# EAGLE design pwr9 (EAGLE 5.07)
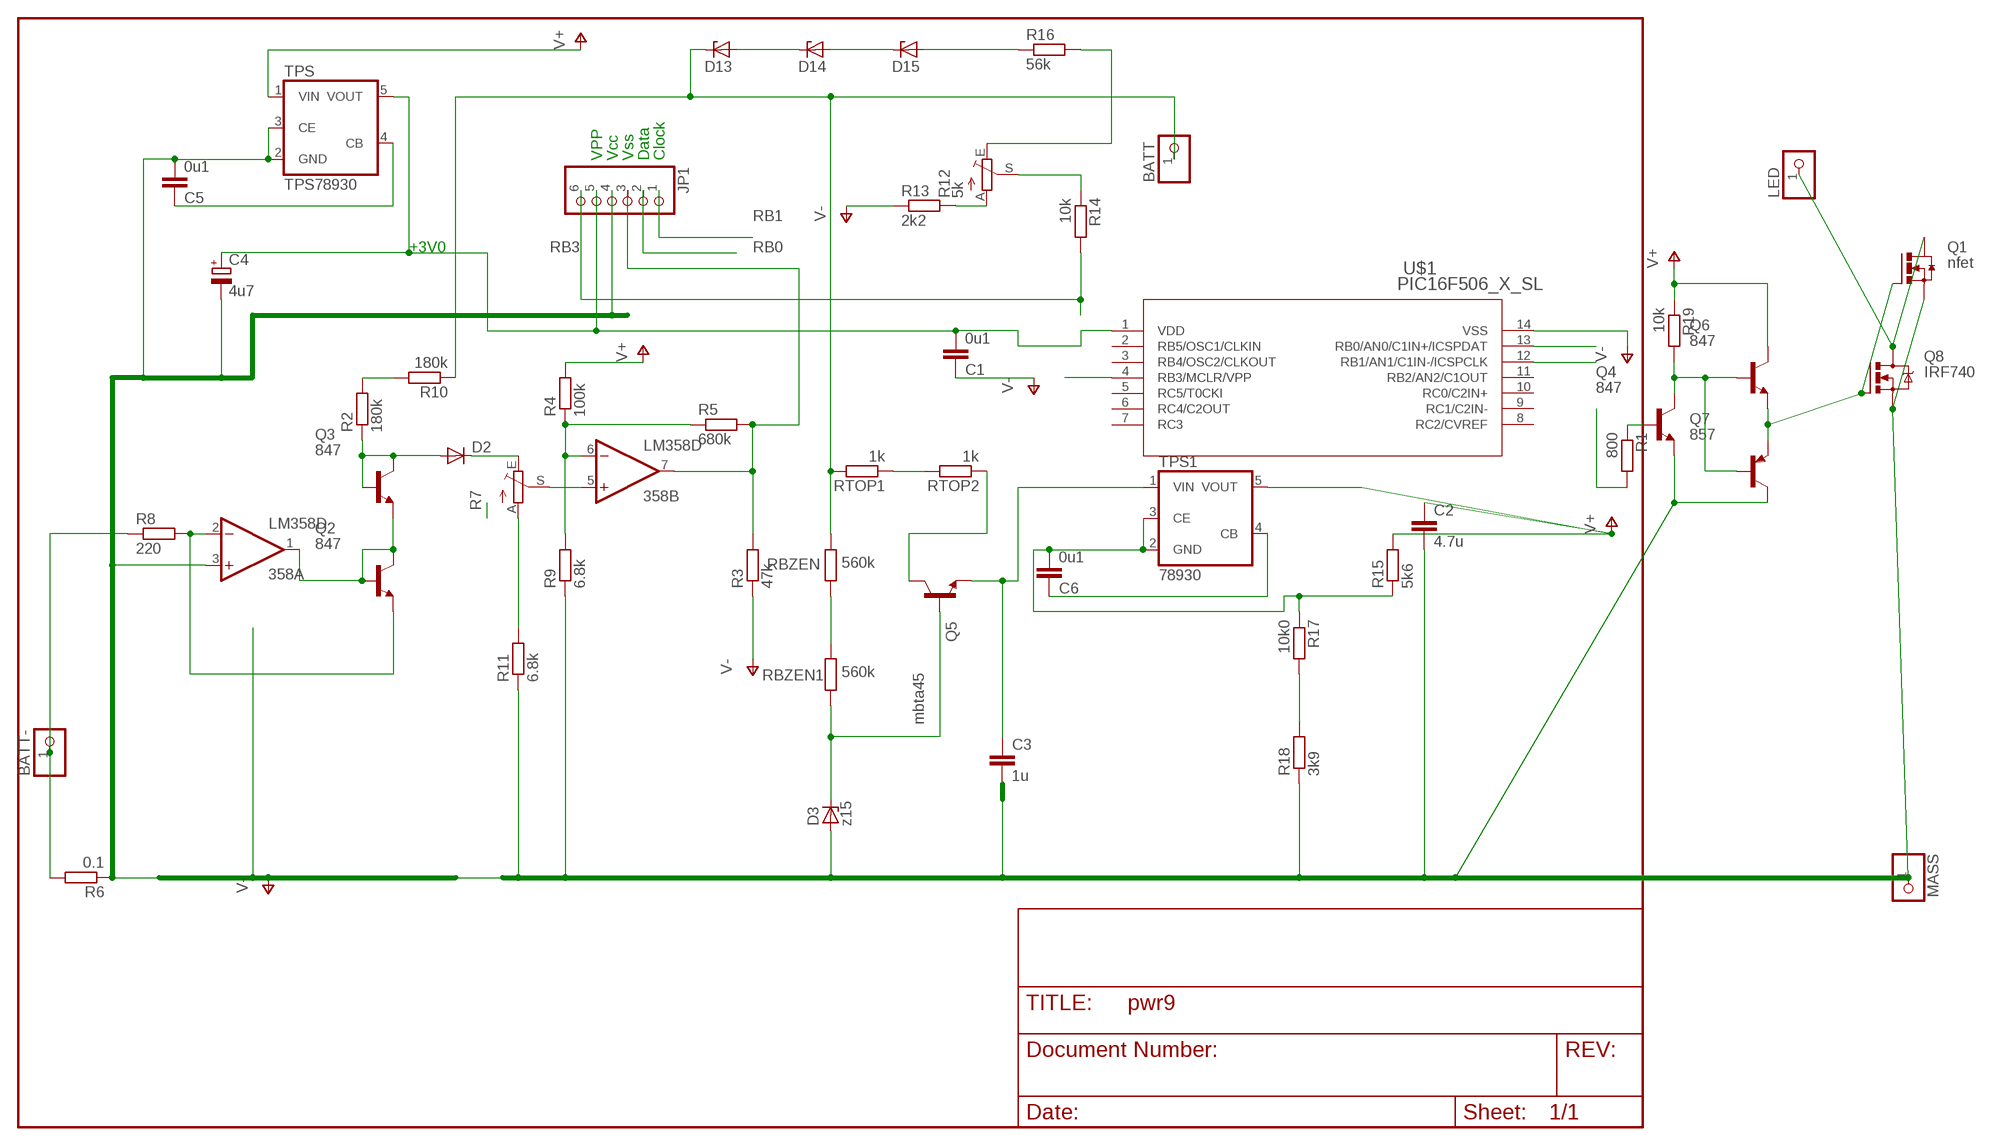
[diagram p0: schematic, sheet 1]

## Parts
358  LM358D  [SO08]
BATT  PINHD-1X1  [1X01]
BATT-  PINHD-1X1  [1X01]
C1  0u1  C-EUC1206  [C1206]
C2  4.7u  C-EUC1206  [C1206]
C3  1u  C-EUC1206  [C1206]
C4  4u7  CPOL-EUSMCA  [SMC_A]
C5  0u1  C-EUC0805  [C0805]
C6  0u1  C-EUC0805  [C0805]
D2  DIODE-SOD80C  [SOD80C]
D3  z15  ZENER-DIODESOD80C  [SOD80C]
D13  ZENER-DIODESOD80C  [SOD80C]
D14  ZENER-DIODESOD80C  [SOD80C]
D15  ZENER-DIODESOD80C  [SOD80C]
JP1  PINHD-1X6  [1X06BOX]
LED  PINHD-1X1  [1X01]
MASS  PINHD-1X1  [1X01]
Q1  nfet  N-HEXFET_DPAK-  [TO252]
Q2  847  BC847ALT1SMD  [SOT23]
Q3  847  BC847ALT1SMD  [SOT23]
Q4  847  BC847ALT1SMD  [SOT23]
Q5  mbta45  BC847ALT1SMD  [SOT23]
Q6  847  BC847ALT1SMD  [SOT23]
Q7  857  BC857ALT1SMD  [SOT23-BEC]
Q8  IRF740  [TO220BV]
R1  800  R-EU_R0805  [R0805]
R2  180k  R-EU_R1206  [R1206]
R3  47k  R-EU_R0805  [R0805]
R4  100k  R-EU_R0805  [R0805]
R5  680k  R-EU_R1206  [R1206]
R6  0.1  R-EU_R2512  [R2512]
R7  TRIM_EU-S64W  [S64W]
R8  220  R-EU_R0805  [R0805]
R9  6.8k  R-EU_R0805  [R0805]
R10  180k  R-EU_R1206  [R1206]
R11  6.8k  R-EU_R0805  [R0805]
R12  5k  TRIM_EU-S64W  [S64W]
R13  2k2  R-EU_R0805  [R0805]
R14  10k  R-EU_R0805  [R0805]
R15  5k6  R-EU_R0805  [R0805]
R16  56k  R-EU_R0805  [R0805]
R17  10k0  R-EU_R0805  [R0805]
R18  3k9  R-EU_R0805  [R0805]
R19  10k  R-EU_R0805  [R0805]
RBZEN  560k  R-EU_R1206  [R1206]
RBZEN1  560k  R-EU_R1206  [R1206]
RTOP1  1k  R-EU_R1206  [R1206]
RTOP2  1k  R-EU_R1206  [R1206]
TPS  TPS78930  TPS78930SOT23-5  [SOT25]
TPS1  78930  TPS78930SOT23-5  [SOT25]
U$1  PIC16F506_X_SL  [SOIC14_N_MC]

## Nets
CB: D3.C Q5.1(B) RBZEN1.2
GND1: C6.1 TPS1.4(CB)
HOT: LED.1 Q1.3(D) Q8.D
N$1: Q4.1(B) R1.1
N$2: R7.A R11.2
N$3: BATT-.1 R6.2 R8.1
N$4: 358.7(B:OUT) JP1.3 R3.2 R5.2
N$5: R1.2
N$6: R2.2 R10.2
N$7: 358.1(A:OUT) Q2.1(B) Q2.3(C) Q3.2(E)
N$9: C1.2 C4.+ JP1.5 TPS.5(VOUT) U$1.1(VDD)
N$10: 358.2(A:-IN) Q2.2(E) R8.2
N$11: C5.1 TPS.4(CB)
N$12: D2.A Q3.1(B) Q3.3(C) R2.1
N$13: D2.C R7.E
N$15: 358.5(B:+IN) R7.S
N$16: Q5.3(C) RTOP2.1
N$17: 358.6(B:-IN) R4.1 R5.1 R9.2
N$18: D15.A R16.1
N$19: RBZEN1.1 RBZEN.2
N$21: Q4.3(C) Q6.1(B) Q7.B R19.2
N$23: D14.A D15.C
N$24: D13.A D14.C
N$25: R12.E R16.2
N$26: R12.A R13.2
N$27: R12.S R14.1
N$28: R17.2 R18.2
N$29: RTOP1.1 RTOP2.2
N$31: Q1.1(G) Q6.2(E) Q7.E Q8.G
RB0: JP1.2 U$1.13(RB0/AN0/C1IN+/ICSPDAT)
RB1: JP1.1 U$1.12(RB1/AN1/C1IN-/ICSPCLK)
RB3: JP1.6 R14.2 U$1.4(RB3/MCLR/VPP)
V15: C3.1 Q5.2(E) TPS1.1(VIN)
V+: C2.1 Q6.3(C) R4.2 R15.2 R19.1 TPS1.5(VOUT) TPS.1(VIN)
V-: 358.3(A:+IN) C1.1 C2.2 C3.2 C4.- C5.2 C6.2 D3.A JP1.4 MASS.1 Q1.2(S) Q4.2(E) Q7.C Q8.S R3.1 R6.1 R9.1 R11.1 R13.1 R15.1 R17.1 R18.1 TPS1.2(GND) TPS1.3(CE) TPS.2(GND) TPS.3(CE) U$1.14(VSS)
VPLUS: BATT.1 D13.C R10.1 RBZEN.1 RTOP1.2
Unconnected: U$1.2(RB5/OSC1/CLKIN) U$1.3(RB4/OSC2/CLKOUT) U$1.5(RC5/T0CKI) U$1.6(RC4/C2OUT) U$1.7(RC3) U$1.8(RC2/CVREF) U$1.9(RC1/C2IN-) U$1.10(RC0/C2IN+) U$1.11(RB2/AN2/C1OUT)

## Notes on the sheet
- VPP | Vcc | Vss | Data | Clock
- +3V0

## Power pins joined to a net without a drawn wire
V+: 358.8(P:V+)
V-: 358.4(P:V-)

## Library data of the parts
358 = linear:LM358: OP AMP also LM158; LM258; LM2904 Source: http://cache.national.com/ds/LM/LM158.pdf
BATT BATT- LED MASS = pinhead:PINHD-1X1: PIN HEADER
C1-C3 C5 C6 = rcl:C-EU: CAPACITOR, European symbol
C4 = rcl(2):CPOL-EU: POLARIZED CAPACITOR, European symbol
D2 = diode:DIODE-: DIODE
D3 D13-D15 = diode:ZENER-DIODE: Z-Diode
JP1 = pinhead:PINHD-1X6: PIN HEADER
Q1 = transistor-power:N-HEXFET_?-*: HEXFET® Power MOSFET
Q2-Q6 = transistor-npn:BC847*: NPN Transistor
Q7 = transistor-pnp:BC857*: PNP Transistror
Q8 = transistor-power:IRF740: N-CHANNEL MOS FET
R1-R6 R8-R11 R13-R19 RBZEN RBZEN1 RTOP1 RTOP2 = rcl:R-EU_: RESISTOR, European symbol
R7 R12 = pot:TRIM_EU-: POTENTIOMETER
TPS TPS1 = v-reg:TPS78930
U$1 = pic16f506mc:PIC16F506_X_SL

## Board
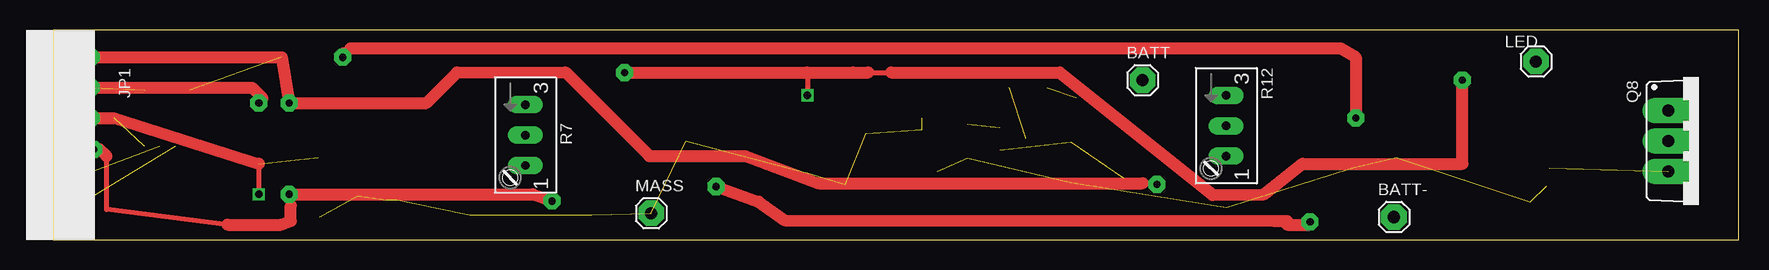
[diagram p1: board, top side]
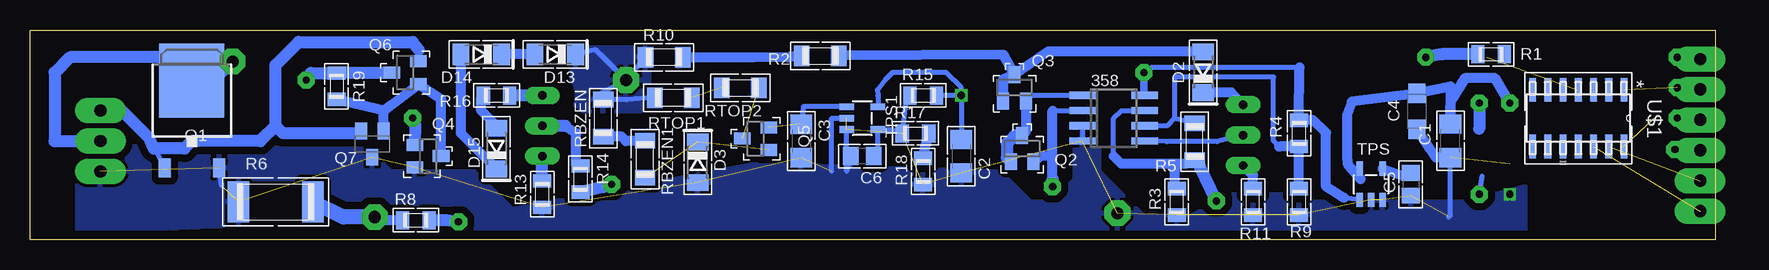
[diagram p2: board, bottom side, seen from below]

Size 140.49 x 17.5 mm. Coordinates in mm from the lower left corner, seen from the top.
Outline: 0,0 140.49,0 140.49,17.5 0,17.5 0,0
Copper layers (1*16): Top 0.035mm / dielectric 1.5mm / Bottom 0.035mm
Design rules "default *": minimum track width 10mil, minimum drill 24mil, track to track 8mil, track to pad 8mil, pad to pad 8mil, via to via 8mil, smd to smd 8mil, copper to edge 30mil, drill to drill 8mil, minimum pad ring 15mil, minimum via ring 8mil, stop-mask expansion 4mil, vias tented up to drill 0mil, thermal gap 10mil

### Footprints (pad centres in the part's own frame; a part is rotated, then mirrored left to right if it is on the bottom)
SO08 = smd 0.6 x 2.2: 1 -1.905,-2.6; 2 -0.635,-2.6; 3 0.635,-2.6; 4 1.905,-2.6; 5 1.905,2.6; 6 0.635,2.6; 7 -0.635,2.6; 8 -1.905,2.6
1X01 = drill 1.016 octagon: 1 0,0
C1206 = smd 1.6 x 1.8: 1 -1.4,0; 2 1.4,0
SMC_A = smd 1.6 x 1.4: + -1.5,0; - 1.5,0
C0805 = smd 1.3 x 1.5: 1 -0.95,0; 2 0.95,0
SOD80C = smd 1.4 x 1.8: A 1.7,0; C -1.7,0
1X06BOX = drill 1.016 long: 1 -6.35,0; 2 -3.81,0; 3 -1.27,0; 4 1.27,0; 5 3.81,0; 6 6.35,0
TO252 = smd 1 x 1.6: 1 -2.28,-3.53; 2 2.28,-3.53 | smd 5.4 x 6.2: 3 0,3.77
SOT23 = smd 1 x 1.4: 1 -0.95,-1.1; 2 0.95,-1.1; 3 0,1.1
SOT23-BEC = smd 1 x 1.4: B -0.95,-1.1; C 0,1.1; E 0.95,-1.1
TO220BV = drill 1.016 long: D 0,-2.54; G -2.54,-2.54; S 2.54,-2.54
R0805 = smd 1.1 x 1.5: 1 -1.1,0; 2 1.1,0
R1206 = smd 1.3 x 1.7: 1 -1.55,0; 2 1.55,0
R2512 = smd 1.8 x 3.4: 1 -3.1,0; 2 3.1,0
S64W = drill 0.7 long: A 2.54,1.27; E -2.54,1.27; S 0,1.27
SOT25 = smd 0.55 x 1.2: 1 -0.95,-1.3; 2 0,-1.3; 3 0.95,-1.3; 4 0.95,1.3; 5 -0.95,1.3
SOIC14_N_MC = smd 1.981 x 0.559: 1 -2.362,3.81; 2 -2.362,2.54; 3 -2.362,1.27; 4 -2.362,0; 5 -2.362,-1.27; 6 -2.362,-2.54; 7 -2.362,-3.81; 8 2.362,-3.81; 9 2.362,-2.54; 10 2.362,-1.27; 11 2.362,0; 12 2.362,1.27; 13 2.362,2.54; 14 2.362,3.81

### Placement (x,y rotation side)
358  50.17,10.16 270 bottom
BATT  90.81,13.34 0 top
BATT-  111.76,1.91 0 top
C1  22.09,8.26 90 bottom
C2  62.86,6.99 270 bottom
C3  76.2,8.26 270 bottom
C4  24.89,10.73 270 bottom
C5  25.4,4.63 270 bottom
C6  71.12,6.99 180 bottom
D2  42.7,14 90 bottom
D3  84.84,6.48 270 bottom
D13  96.71,15.5 180 bottom
D14  102.87,15.5 180 bottom
D15  101.6,7.62 90 bottom
JP1  1.27,8.75 90 top
LED  123.6,14.89 0 top
MASS  49.85,2.22 0 top
Q1  127,9.53 0 bottom
Q2  57.78,7.62 0 bottom
Q3  58.42,12.7 0 bottom
Q4  107.31,6.99 270 bottom
Q5  80.01,8.45 90 bottom
Q6  109.22,13.97 90 bottom
Q7  111.95,8 180 bottom
Q8  137.16,8.26 270 top
R1  18.7,15.5 0 bottom
R2  74.61,15.37 180 bottom
R3  44.89,3.17 90 bottom
R4  34.7,8.89 90 bottom
R5  43.4,8.2 270 bottom
R6  120.02,3.17 0 bottom
R7  38.1,8.75 270 top
R8  108.33,1.65 0 bottom
R9  34.7,3.17 90 bottom
R10  87.63,15.24 0 bottom
R11  38.54,3.17 90 bottom
R12  96.52,9.53 270 top
R13  97.79,3.81 90 bottom
R14  94.62,5.08 270 bottom
R15  66.04,12.06 0 bottom
R16  101.6,12.06 0 bottom
R17  66.67,8.89 0 bottom
R18  66.04,5.71 90 bottom
R19  114.94,12.83 270 bottom
RBZEN  92.71,10.16 270 bottom
RBZEN1  89.22,6.73 270 bottom
RTOP1  86.87,11.87 180 bottom
RTOP2  81.28,12.7 180 bottom
TPS  28.7,4.63 0 bottom
TPS1  71.12,10.16 270 bottom
U$1  11.43,10.16 270 bottom

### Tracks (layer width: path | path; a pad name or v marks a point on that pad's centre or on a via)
CB  (2 unrouted)
GND1
  Bottom 0.406: C6.1 69.82,7.62 TPS1.4 68.58,9.21 67.8,8.72
HOT
  Bottom 1.016: LED.1 125.2,13.29 Q1.3 127.64,13.29 129.58,15.24 137.16,15.24 138.43,13.97 138.43,8.26 Q8.D
N$1  (via drill 0.6 pad 1.42)
  Top 0.406: v24.13,15.24 24.13,15.88 24.77,16
  Top 1.016: 24.77,16 107.31,16 108.59,15.24 v108.59,10.16
  Bottom 0.406: v108.59,10.16 108.39,9.69
  Bottom 1.016: R1.1 22.79,15.49 v24.13,15.24 | 108.39,9.69 Q4.1
N$2
  Bottom 0.813: R11.2 38.55,5.38 R7.A
N$3
  Bottom 0.406: 111.51,1.65 BATT-.1
  Bottom 0.813: R8.1 111.51,1.65
  Bottom 1.27: BATT-.1 114.38,1.91 R6.2
N$4  (via drill 0.6 pad 1.42)
  Top 0.406: 4.44,6.99 4.44,2.54 14.54,1.27 | 19.81,2.86 v19.68,3.81
  Top 1.016: v41.59,3.24 40,3.81 v19.68,3.81 | 14.54,1.27 18.99,1.27 19.81,1.59 19.81,2.86 | v3.36,7.56 3.87,7.56 4.44,6.99
  Bottom 0.406: v19.68,3.81 19.43,5.33 | 358.7 49.53,10.79 50.17,10.16 50.17,6.99 | 45.08,4.85 R3.2 | R5.2 42.96,6.13 44.13,6.35
  Bottom 0.813: 50.17,6.99 49.53,6.35 45.08,6.35 | 44.13,6.35 45.08,6.35 | 45.08,6.35 45.08,4.85
  Bottom 1.016: v41.59,3.24 42.96,6.13 | JP1.3 3.29,7.48 v3.36,7.56
N$6
  Bottom 0.406: 85.57,15.23 R10.2
  Bottom 0.813: R2.2 77.28,15.24 80.14,15.23 85.57,15.23
N$7
  Bottom 0.406: 358.1 57,12.06 Q3.2 | 57.47,9.04 Q2.3
  Bottom 0.813: Q3.2 57.47,9.04
  Bottom 1.016: Q2.3 58.4,8.72 59.05,8.06 59.05,6.84 Q2.1
N$9  (via drill 0.6 pad 1.42)  (1 unrouted)
  Top 0.406: 17.45,11.83 17.45,11.74 v17.14,11.43
  Top 1.016: v3.17,12.7 16.58,12.7 17.45,11.83
  Bottom 0.406: 29.55,5.08 TPS.5
  Bottom 0.813: 29.55,5.08 30.67,6.35 30.7,7.05 30.7,10.41 30.31,11.53 C4.+ 22.06,12.8 C1.2 22.09,11.56 20.89,13.5 18.35,13.5 v17.14,11.43
  Bottom 1.016: JP1.5 3.04,12.56 v3.17,12.7
N$10  (via drill 0.6 pad 1.42)
  Top 0.406: 102.87,1.59 102.87,1.27 | 104.78,1.27 v104.78,1.5
  Top 1.016: 102.87,1.59 101.79,1.59 60.96,1.64 58.8,3.17 v55.25,4.45 | 102.87,1.27 104.78,1.27
  Bottom 0.406: 55.25,10.79 358.2
  Bottom 0.813: 55.25,6.99 55.25,10.79 | 55.25,5.08 55.25,6.99 | Q2.2 56.26,6.98 55.25,6.99
  Bottom 1.016: R8.2 105.79,1.65 v104.78,1.5 | v55.25,4.45 55.25,5.08
N$11
  Bottom 0.813: C5.1 25.94,5.36 26,5.3 TPS.4
N$12
  Bottom 0.406: 55.53,15.7 55.58,15.75
  Bottom 0.813: 55.58,15.75 Q3.3 | Q3.1 59.37,13.42 Q3.3 | R2.1 59.33,15.44 Q3.3 | D2.A 55.53,15.7
N$13
  Bottom 0.406: R7.E 40.16,12.08
  Bottom 0.813: D2.C 40.38,12.3 R7.E
N$15
  Bottom 0.406: R7.S 41.54,8.2 45.72,8.2 358.5
N$16  (1 unrouted)
N$17
  Bottom 0.406: 358.6 45.72,9.53 45.08,10.16 | 45.08,10.16 44.16,9.97 R5.1 | 36.36,7.79 36.83,8.26 36.83,13.6 45.08,13.6 45.08,10.16
  Bottom 0.813: 36.36,7.79 R4.1 R9.2
N$18
  Bottom 0.406: D15.A 101.6,9.53 | 102.87,11.89 R16.1
  Bottom 0.813: 101.6,9.53 102.87,10.79 102.87,11.89
N$19
  Bottom 0.406: RBZEN1.1 89.89,8.26
  Bottom 0.813: RBZEN.2 91.16,8.61 90.81,8.26 89.89,8.26
N$21
  Bottom 0.406: Q7.B 111,10.78 | Q6.1 108.44,12.7
  Bottom 0.813: Q4.3 106.22,11.75 Q6.1 | 111,10.78 R19.2 | Q7.B 111.06,10.73 110.3,11.3 108.44,12.7
N$23
  Bottom 0.813: D14.A 104.57,8.89 D15.C
N$24
  Bottom 0.406: D13.A 99.06,15.5
  Bottom 0.813: 99.06,15.5 D14.C
N$25
  Bottom 1.016: R12.E R16.2
N$26
  Bottom 1.016: R13.2 R12.A
N$27
  Bottom 0.406: R14.1 94.95,6.18
  Bottom 0.813: 95.89,9.53 94.95,8.89 94.95,6.18
  Bottom 1.016: 95.89,9.53 R12.S
N$28
  Bottom 0.813: R18.2 R17.2
N$29  (1 unrouted)
N$31
  Bottom 0.406: 108.07,15.87 Q6.2 | Q7.E 113.52,8.89 | 130.55,8.52 Q1.1
  Bottom 1.016: 108.07,15.87 108.59,16.51 118.11,16.51 120.02,14.61 120.02,9.53 | 120.02,9.53 119.38,8.89 113.52,8.89 | 120.02,9.53 121.28,8.26 127,8.26 127.64,7.62 130.17,7.62 130.55,8.52 132.83,10.79 Q8.G
RB0  (1 unrouted)
RB1  (1 unrouted)
RB3  (via drill 0.6 pad 1.42)  (1 unrouted)
  Top 0.406: 90.81,4.71 v92.01,4.64
  Top 1.016: 90.81,4.71 63.8,4.71 57.7,7 49.7,7 42.7,14 33.66,13.97 31.11,11.43 v19.68,11.43 19.05,15.24 v3.17,15.24
  Bottom 0.406: v92.01,4.64 92.71,4.4
  Bottom 1.016: 92.71,4.4 R14.2 | v19.68,11.43 19.68,9.27 | JP1.6 3.04,15.1 v3.17,15.24
V15  (1 unrouted)
  Bottom 0.406: TPS1.1 76.02,11.11 C3.1
V+  (via drill 0.6, 0.6 pad 1.42)
  Top 0.406: 62.86,13.97 v62.86,12.06 | 66.67,13.97 69.85,13.97
  Top 1.016: v117.48,13.34 117.48,6.35 104.14,6.35 100.97,3.81 96.65,3.75 83.88,13.97 69.85,13.97 | v47.62,13.97 62.86,13.97 66.67,13.97 67.94,13.97
  Bottom 0.406: TPS.1 30.95,3.53 | R19.1 114.07,13.97 | 34.67,14.4 46.99,14.4 v47.62,13.97 | 47.62,12.12 358.8 | v62.86,12.06 C2.1 | v62.86,12.06 62.86,12.7 64.14,13.97 68.58,13.97 69.22,13.34 69.85,12.51 69.82,12.04 TPS1.5 | v62.86,12.06 R15.2
  Bottom 0.61: v47.62,13.97 47.62,12.12
  Bottom 0.813: 30.95,3.53 32.45,4.45 32.45,8.95 33.55,9.99 R4.2 34.67,14.4
  Bottom 1.016: R19.1 117.07,13.93 v117.48,13.34 | 114.07,13.97 Q6.3
V-  (via drill 0.6, 0.6 pad 1.42)  (23 unrouted)
  Top 0.406: 17.14,6.35 v17.14,3.81
  Top 1.016: v3.17,10.16 5.08,10.16 17.14,6.35
  Bottom 0.406: 124.52,4.52 Q1.2 | C6.2 72.42,5.71 TPS1.3 | TPS1.2 73.66,10.16 73.66,5.71 | C1.1 22.09,2.04 22.23,1.91 | 358.3 358.4 | R15.1 67.48,11.43 R17.1
  Bottom 0.813: C1.1 23.28,6.86 C4.-
  Bottom 1.016: JP1.4 3.04,10.02 v3.17,10.16
  pour Bottom (isolate 0.61): 15.88,4.45 15.88,0.64 104.14,0.64 105.41,1.91 113.67,1.91 116.84,5.08 122.56,5.08 122.56,1.27 136.53,0.64 136.53,6.99 127.64,8.89 113.67,8.89 110.49,5.71 103.51,5.71 100.33,2.54 80.01,6.35 59.69,5.71 57.15,3.17 55.25,3.17 53.34,5.08 53.34,8.26 53.97,8.89 52.7,8.89 51.44,7.62 51.44,5.71 47.62,1.91 43.81,1.91 40.64,3.81 34.92,3.81 34.92,3.17 19.05,3.17 18.41,3.81
VPLUS
  Bottom 0.406: D13.C 93.34,15.88 BATT.1 | BATT.1 92.71,12.35 RBZEN.1 90.73,11.71 RTOP1.2 | BATT.1 R10.1
  pour Bottom (isolate 1.27): 88.9,17.14 94.62,17.14 95.25,15.88 95.25,11.43 94.62,10.79 89.53,10.79 88.9,11.43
